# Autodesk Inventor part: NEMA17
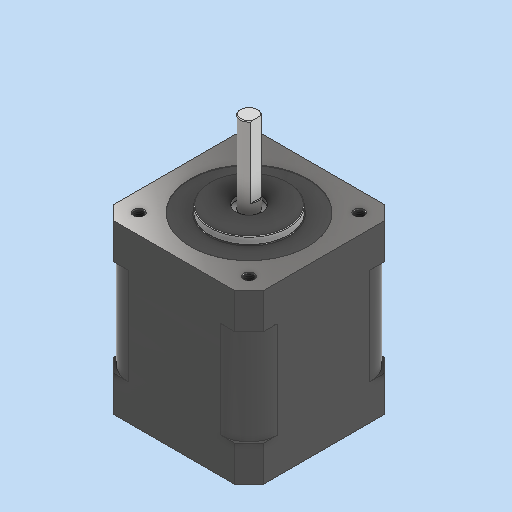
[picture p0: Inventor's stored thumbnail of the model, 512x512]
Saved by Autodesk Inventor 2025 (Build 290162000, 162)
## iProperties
Created: 2023-09
Part Number: NEMA17
Material: Genérico
Document SubType Name: Modeling
Designer: USUARIO
Density: 1 g/cm^3
Appearance: Valor por defecto
Author: USUARIO
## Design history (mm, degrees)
node "Annotazioni"
  node "Quota lineare 1" dims "d17" = 31, "d141" = 42 (derived)
  node "Quota lineare 2" dims "d17" = 31, "d144" = 42 (derived)
  node "Quota lineare 3" dims "d17" = 31, "d146" = 47.15 (derived)
  node "Quota lineare 4" dims "d17" = 31, "d149" = 22 (derived)
  node "Quota lineare 5" dims "d17" = 31, "d150" = 31 (derived)
sketch "Boceto1"
  geometry: L1 (0, 0)-(42, 0); L2 (42, 0)-(42, -42); L3 (42, -42)-(0, -42); L4 (0, -42)-(0, 0)
  constraints: 8 end point, 2 parallel, 1 horizontal, 1 perpendicular
  dimensions: "d105" = 42 distance of L2.end L3.end; "d106" = 42 distance of L1.end L2.end
extrude "Extrusión1" new body sketch "Boceto1" distance "d10" = 47.15; taper "d11" = 0 deg
sketch "Boceto2"
  geometry: L1 (-4, 42)-(-38, 42) reference; L2 (-38, 42)-(-42, 38) reference; L3 (-42, 38)-(-42, 4) reference; L4 (-42, 4)-(-38, 0) reference; L5 (-38, 0)-(-4, 0) reference; L6 (-4, 0)-(0, 4) reference; L7 (0, 4)-(0, 38) reference; L8 (0, 38)-(-4, 42) reference; L9 (-42, 38)-(-42, 4) reference; L10 (-42, 21)-(0, 21); L11 (-38, 0)-(-4, 0) reference; L12 (-21, 0)-(-21, 42); C1 r 11 at (-21, 21); C2 r 1.25 at (-36.5, 5.5); C3 r 1.25 at (-36.5, 36.5); C4 r 1.25 at (-5.5, 36.5); C5 r 1.25 at (-5.5, 5.5); C6 r 2.5 at (-21, 21); C7 r 16.5 at (-21, 21); 1 further point
  constraints: 7 centre point, 5 midpoint, 4 end point, 4 symmetric about line, 2 coincident
  dimensions: "d12" = 22 diameter of C1; "d13" = 2.5 diameter of C2; "d14" = 2.5 diameter of C3; "d15" = 2.5 diameter of C4; "d16" = 2.5 diameter of C5; "d17" = 31 distance of C3.centre C2.centre; "d18" = 31 distance of C4.centre C3.centre; "d19" = 5 diameter of C6; "d63" = 33 diameter of C7
  node "Contorno proyectado1"
extrude "Extrusión2" join sketch "Boceto2" distance "d20" = 2; taper "d21" = 0 deg
extrude "Extrusión3" join sketch "Boceto2" distance "d22" = 24; taper "d23" = 0 deg
hole "Agujero1" sketch "Boceto2" diameter "d24" = 2.5; stored, may be unused: countersink angle "d28" = 90 deg, drill point angle "d30" = 118 deg; dims "d25" = 6, "d26" = 3, "d27" = 2, "d29" = 4.5
extrude "Extrusión10" cut sketch "Boceto2" distance "d64" = 0.2; taper "d65" = 0 deg
fillet "Empalme1" dims "d66" = 0.2
sketch "Boceto11"
  geometry: C1 r 2.5 at (0, 0) reference; C2 r 3.75 at (0, 0); 1 further point
  constraints: 1 centre point, 1 coincident
  dimensions: "d67" = 7.5 diameter of C2
extrude "Extrusión11" cut sketch "Boceto11" distance "d68" = 1; taper "d69" = 0 deg
fillet "Empalme2" dims "d70" = 0.2
fillet "Empalme3" dims "d71" = 0.2
sketch "Boceto12"
  geometry: L1 (-4, -42)-(-38, -42) reference; L2 (0, -38)-(-4, -42) reference; L3 (0, -4)-(0, -38) reference; L4 (-4, 0)-(0, -4) reference; L5 (-38, 0)-(-4, 0) reference; L6 (-42, -4)-(-38, 0) reference; L7 (-42, -38)-(-42, -4) reference; L8 (-38, -42)-(-42, -38) reference; C1 r 3.75 at (-21, -21) reference; C2 r 1.25 at (-36.5, -5.5) reference; C3 r 1.25 at (-36.5, -5.5); C4 r 1.25 at (-5.5, -5.5); C5 r 1.25 at (-36.5, -36.5); C6 r 1.25 at (-5.5, -36.5); 1 further point
  constraints: 4 centre point, 1 coincident, 1 horizontal, 1 vertical, 6 other
  dimensions: "d74" = 31 distance of C3.centre C4.centre; "d77" = 31 distance of C3.centre C5.centre
  node "Contorno proyectado7"
  node "Schizzo - Serie rettangolare2" dims "d74" = 31, "d77" = 31
extrude "Extrusión12" cut sketch "Boceto12" distance "d80" = 1.5; taper "d81" = 0 deg
hole "Agujero2" sketch "Boceto12" diameter "d82" = 2.5; stored, may be unused: countersink angle "d86" = 90 deg, drill point angle "d88" = 118 deg; dims "d83" = 6, "d84" = 3, "d85" = 2, "d87" = 4.5
feature "Rosca1" dims "d89" = 4.25, "d90" = 0
feature "Rosca2" dims "d91" = 4.25, "d92" = 0
feature "Rosca3" dims "d93" = 4.25, "d94" = 0
feature "Rosca4" dims "d95" = 4.25, "d96" = 0
feature "Rosca5" dims "d97" = 4.25, "d98" = 0
feature "Rosca6" dims "d99" = 4.25, "d100" = 0
feature "Rosca7" dims "d101" = 4.25, "d102" = 0
feature "Rosca8" dims "d103" = 4.25, "d104" = 0
sketch "Schizzo13"
  geometry: L1 (2, 1.5)-(2, -1.5); A1 r 2.5 centre (0, 0) between (2, 1.5) and (2, -1.5) reference; A2 r 2.5 centre (0, 0) between (2, 1.5) and (2, -1.5) reference; 1 further point
  constraints: 2 end point, 2 point on circle, 1 vertical
  dimensions: "d107" = 2 distance from line of A1.centre L1
extrude "Estrusione13" cut sketch "Schizzo13" distance "d108" = 20; taper "d109" = 0 deg
sketch "Schizzo14"
  geometry: L1 (0, 0)-(0, 47.15) reference; L2 (42, 0)-(42, 47.15) reference; L3 (0, 37.15)-(42, 37.15); L4 (42, 37.15)-(42, 10); L5 (42, 10)-(0, 10); L6 (0, 10)-(0, 37.15); L7 (0, 47.15)-(42, 47.15) reference; L8 (0, 0)-(42, 0) reference; L9 (0, 0)-(42, 0) reference; L10 (42, 0)-(42, 47.15) reference; L11 (0, 47.15)-(42, 47.15) reference; L12 (0, 0)-(0, 47.15) reference; 2 further points
  constraints: 8 end point, 2 parallel, 2 point on line, 1 horizontal, 1 perpendicular
  dimensions: "d110" = 10 distance between parallel lines of L7 L3; "d111" = 10 distance between parallel lines of L8 L5
extrude "Estrusione14" cut sketch "Schizzo14" extent not by distance; stored distance "d112" = 0; taper "d113" = 0 deg
sketch "Schizzo15"
  geometry: L1 (42, 42)-(0, 42) reference; L2 (8, 42)-(34, 42); L3 (42, 34)-(42, 8); L4 (34, 0)-(8, 0); L5 (0, 8)-(0, 34); A1 r 8 centre (8, 34) between (8, 42) and (0, 34); A2 r 8 centre (8, 8) between (0, 8) and (8, 0); A3 r 8 centre (34, 8) between (34, 0) and (42, 8); A4 r 8 centre (34, 34) between (42, 34) and (34, 42); 3 further points
  constraints: 8 end point, 8 point on circle, 8 tangent, 4 centre point, 4 point on line, 3 equal radius, 2 parallel, 1 horizontal, 1 perpendicular
  dimensions: "d114" = 8 radius of A1
extrude "Estrusione15" join sketch "Schizzo15" stored distance "d115" = 10; taper "d116" = 0 deg
sketch "Schizzo16"
  geometry: L1 (-42, 42)-(-42, 0) reference; L2 (-4, 0)-(-38, 0); L3 (-42, 4)-(-42, 38); L4 (-38, 42)-(-4, 42); L5 (0, 38)-(0, 4); L6 (-4, 0)-(0, 4); L7 (0, 38)-(-4, 42); L8 (-38, 42)-(-42, 38); L9 (-42, 4)-(-38, 0); L10 (0, 42)-(-42, 42) reference; L11 (-42, 42)-(-42, 0) reference; L12 (-42, 0)-(0, 0) reference; L13 (0, 0)-(0, 42) reference; C1 r 16.5 at (-21, 21) reference; C2 r 1.5 at (-5.5, 36.5) reference; C3 r 1.5 at (-36.5, 5.5) reference; C4 r 1.5 at (-36.5, 36.5) reference; C5 r 1.5 at (-5.5, 5.5) reference; 13 further points
  constraints: 16 end point, 8 point on line, 2 parallel, 1 horizontal, 1 perpendicular
  dimensions: "d117" = 4 distance of L2.start point (0, 0); "d118" = 4 distance of L5.end point (0, 0) (= d117); "d119" = 4 distance of L5.start point (0, 42) (= d117); "d120" = 4 distance of L4.end point (0, 42) (= d119); "d121" = 4 distance of L4.start L1.start (= d117); "d122" = 4 distance of L3.end L1.start (= d121); "d123" = 4 distance of L3.start point (-42, 0) (= d117); "d124" = 4 distance of L2.end point (-42, 0) (= d123)
extrude "Estrusione16" cut sketch "Schizzo16" extent not by distance; stored distance "d125" = 0; taper "d126" = 0 deg
sketch "Schizzo18"
  geometry: L1 (9.568, -0.165)-(16.432, -0.165); L2 (16.432, -0.165)-(16.432, -6.785); L3 (16.432, -6.785)-(9.568, -6.785); L4 (9.568, -6.785)-(9.568, -0.165); L5 (16.75, -10)-(9.25, -10) reference; L6 (13, -10)-(13, -24.174); 1 further point
  constraints: 10 end point, 2 parallel, 1 horizontal, 1 midpoint, 1 perpendicular, 1 vertical, 1 other
extrude "Estrusione17" cut sketch "Schizzo18" distance "d127" = 1; taper "d128" = 0 deg
sketch "Schizzo19"
  geometry: L1 (26, 0)-(26, 27.15) reference; L2 (0, 0)-(0, 27.15) reference; L3 (24, 21.689)-(2, 21.689); L4 (0, 19.689)-(0, 10.651); L5 (2, 8.651)-(24, 8.651); L6 (26, 10.651)-(26, 19.689); A1 r 2 centre (2, 19.689) between (2, 21.689) and (0, 19.689); A2 r 2 centre (2, 10.651) between (0, 10.651) and (2, 8.651); A3 r 2 centre (24, 10.651) between (24, 8.651) and (26, 10.651); A4 r 2 centre (24, 19.689) between (26, 19.689) and (24, 21.689); 7 further points
  constraints: 8 end point, 8 point on circle, 8 tangent, 6 point on line, 4 centre point, 3 equal radius, 2 parallel, 1 horizontal, 1 perpendicular
  dimensions: "d129" = 2 radius of A1
extrude "Estrusione18" join sketch "Schizzo19" distance "d130" = 0.1; taper "d131" = 0 deg
sketch "Schizzo20"
  geometry: L1 (1.768, 19.705)-(23.84, 19.705); L2 (23.84, 19.705)-(23.84, 17.952); L3 (23.84, 17.952)-(1.768, 17.952); L4 (1.768, 17.952)-(1.768, 19.705); L5 (2.541, 14.6)-(25.13, 14.6); L6 (25.13, 14.6)-(25.13, 11.608); L7 (25.13, 11.608)-(2.541, 11.608); L8 (2.541, 11.608)-(2.541, 14.6)
  constraints: 4 other
sketch "Schizzo21"
  geometry: C1 r 0.625 at (11.812, -2.461); C2 r 0.625 at (13.519, -2.461); C3 r 0.625 at (11.812, -4.013); C4 r 0.625 at (13.344, -4.013); 1 further point
  constraints: 4 centre point
  dimensions: "d132" = 1.25 diameter of C1; "d133" = 1.25 diameter of C2; "d134" = 1.25 diameter of C3; "d135" = 1.25 diameter of C4
extrude "Estrusione19" join sketch "Schizzo21" distance "d136" = 5; taper "d137" = 0 deg
fillet "Raccordo4" dims "d138" = 1
node "Sólido1"
node "Contorno proyectado6"
node "Linea chiusa proiettata8"
node "Linea chiusa proiettata9"
other parameters: "d31" = 19, "d139" = 7.70626 (derived), "d140" = 4.62744 (derived), "d142" = 1.65694 (derived), "d143" = 6.49634 (derived), "d145" = 8.63576 (derived), "d147" = 5.02646 (derived), "d148" = 4.17721 (derived)
